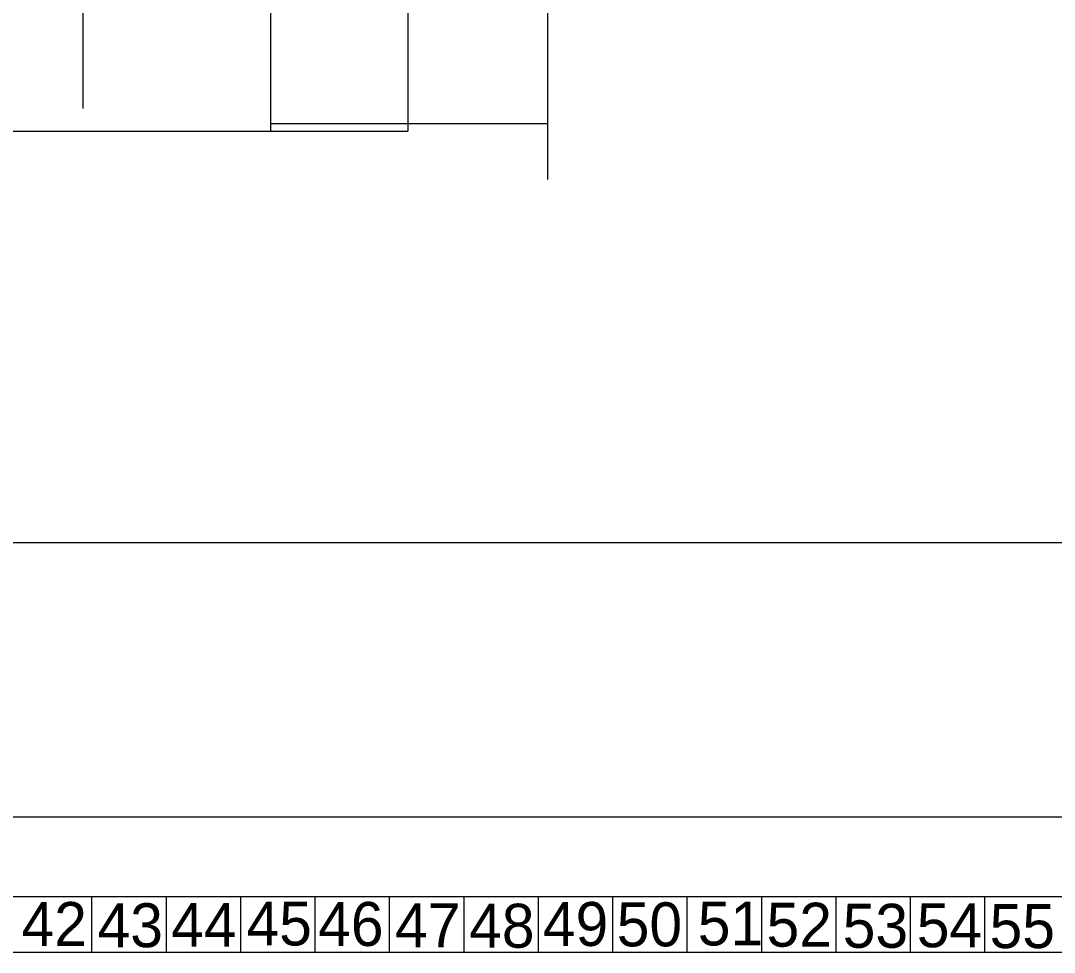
# Model space of a CAD drawing. Extents: x -0.08 to 2.83, y -0.03 to 1.92.
# Drawn here: x 0.8 to 1.0352, y -0.0307 to 0.1812 of the extents above; entities that cross this region are included whole.
import ezdxf

# ---------------------------------------------------------------- set-up
doc = ezdxf.new("R2010")
doc.units = 0
for name, color, linetype in [('42', 7, 'Continuous'), ('43', 7, 'Continuous'), ('44', 7, 'Continuous'), ('45', 7, 'Continuous'), ('46', 7, 'Continuous'), ('47', 7, 'Continuous'), ('48', 7, 'Continuous'), ('49', 7, 'Continuous'), ('50', 7, 'Continuous'), ('51', 7, 'Continuous'), ('52', 7, 'Continuous'), ('53', 7, 'Continuous'), ('54', 7, 'Continuous'), ('55', 7, 'Continuous'), ('62', 7, 'Continuous'), ('63', 7, 'Continuous')]:
    doc.layers.add(name, color=color, linetype=linetype)

msp = doc.modelspace()

# ---------------------------------------------------------------- linework, layer by layer
at = {"layer": '50'}
for p, q in [((0.91992, 0.14506), (0.91992, 0.33062)), ((0.85684, 0.18731), (0.85684, 0.15606)), ((0.88809, 0.18731), (0.88809, 0.15606)), ((0.85684, 0.15781), (0.91992, 0.15781)), ((0.36956, 0.15607), (0.88809, 0.15607))]:
    msp.add_line(p, q, dxfattribs=at)
at = {"layer": '51'}
for p, q in [((0.81422, 0.16127), (0.81422, 0.47444)), ((0.81431, 0.16127), (0.81431, 0.16127))]:
    msp.add_line(p, q, dxfattribs=at)
at = {"layer": '62'}
for p, q in [((0.10494, -0.01804), (1.17174, -0.01804)), ((0.81614, -0.01804), (0.81614, -0.03074)), ((0.83308, -0.01804), (0.83308, -0.03074)), ((0.85001, -0.01804), (0.85001, -0.03074)), ((0.86694, -0.01804), (0.86694, -0.03074)), ((0.88388, -0.01804), (0.88388, -0.03074)), ((0.90081, -0.01804), (0.90081, -0.03074)), ((0.91774, -0.01804), (0.91774, -0.03074)), ((0.93468, -0.01804), (0.93468, -0.03074)), ((0.95161, -0.01804), (0.95161, -0.03074)), ((0.96854, -0.01804), (0.96854, -0.03074)), ((0.98548, -0.01804), (0.98548, -0.03074)), ((1.00241, -0.01804), (1.00241, -0.03074)), ((1.01934, -0.01804), (1.01934, -0.03074)), ((0.10494, -0.03074), (1.17174, -0.03074))]:
    msp.add_line(p, q, dxfattribs=at)
at = {"layer": '63'}
msp.add_line((2.83333, 0), (0, 0), dxfattribs=at)
msp.add_lwpolyline([(0.16668, 0.06244), (0.16668, 1.77077), (2.72918, 1.77077), (2.72918, 0.10411), (2.56251, 0.10411), (2.56251, 0.14578), (2.07387, 0.14578), (2.07387, 0.06244)], close=True, dxfattribs=at)

# ---------------------------------------------------------------- texts
at = {"layer": '42'}
msp.add_text('42', height=0.01, rotation=360, dxfattribs=at).set_placement((0.8002, -0.0293))
at = {"layer": '43'}
msp.add_text('43', height=0.01, rotation=360, dxfattribs=at).set_placement((0.8175, -0.02958))
at = {"layer": '44'}
msp.add_text('44', height=0.01, rotation=360, dxfattribs=at).set_placement((0.83425, -0.02949))
at = {"layer": '45'}
msp.add_text('45', height=0.01, rotation=360, dxfattribs=at).set_placement((0.85139, -0.02918))
at = {"layer": '46'}
msp.add_text('46', height=0.01, rotation=360, dxfattribs=at).set_placement((0.8677, -0.02929))
at = {"layer": '47'}
msp.add_text('47', height=0.01, rotation=360, dxfattribs=at).set_placement((0.8852, -0.02958))
at = {"layer": '48'}
msp.add_text('48', height=0.01, rotation=360, dxfattribs=at).set_placement((0.90205, -0.02969))
at = {"layer": '49'}
msp.add_text('49', height=0.01, rotation=360, dxfattribs=at).set_placement((0.91882, -0.02929))
at = {"layer": '50'}
msp.add_text('50', height=0.01, rotation=360, dxfattribs=at).set_placement((0.93563, -0.02938))
at = {"layer": '51'}
msp.add_text('51', height=0.01, rotation=360, dxfattribs=at).set_placement((0.95407, -0.02918))
at = {"layer": '52'}
msp.add_text('52', height=0.01, rotation=360, dxfattribs=at).set_placement((0.96972, -0.02946))
at = {"layer": '53'}
msp.add_text('53', height=0.01, rotation=360, dxfattribs=at).set_placement((0.98705, -0.0297))
at = {"layer": '54'}
msp.add_text('54', height=0.01, rotation=360, dxfattribs=at).set_placement((1.0039, -0.02958))
at = {"layer": '55'}
msp.add_text('55', height=0.01, rotation=360, dxfattribs=at).set_placement((1.02047, -0.02978))

doc.saveas('drawing.dxf')
